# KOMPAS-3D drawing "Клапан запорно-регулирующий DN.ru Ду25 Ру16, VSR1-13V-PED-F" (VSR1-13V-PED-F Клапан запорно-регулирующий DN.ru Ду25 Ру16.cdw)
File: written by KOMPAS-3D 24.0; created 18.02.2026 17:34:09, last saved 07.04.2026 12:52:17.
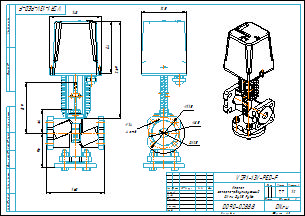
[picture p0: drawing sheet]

Document properties: Автор: R2D2; Форматы листов документа: A3; Полное имя файла: VSR1-13V-PED-F Клапан запорно-регулирующий DN.ru Ду25 Ру16.m3d; Масса: 7.7; Наименование: Клапан запорно-регулирующий DN.ru Ду25 Ру16; Количество листов документа: 1; Примечание: D090-02888

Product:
- Part/product: Клапан запорно-регулирующий DN.ru Ду25 Ру16  | designation VSR1-13V-PED-F
    Масса: 7.7
    Раздел спецификации: Прочие изделия
    Примечание: D090-02888

Views: Вид 1, Спереди
Referenced files in E:\Работа\Зайцев\Солянка\VSR1-13V-PED-F Клапан запорно-регулирующий DN.ru\DN15\DN15 Kv0.16\: VSR1-13V-PED-F Клапан запорно-регулирующий DN.ru Ду15 Ру16.m3d
Referenced files in E:\Работа\Зайцев\Солянка\VSR1-13V-PED-F Клапан запорно-регулирующий DN.ru\DN25\: VSR1-13V-PED-F Клапан запорно-регулирующий DN.ru Ду25 Ру16.m3d
Referenced files in E:\Работа\Зайцев\Для компаса\: чертеж DN.ru А3.cdt
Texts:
  Линейный размер
  VSR1-13V-PED-F
  чертеж DN.ru А3.cdt
  Клапан
  запорно-регулирующий
  DN.ru Ду25 Ру16
  Клапан запорно-регулирующий DN.ru Ду25 Ру16
  VSR1-13V-PED-F Клапан запорно-регулирующий DN.ru Ду25 Ру16
Dimensions and other numbers on the sheet: 0; 3; 2; 4; 160; 143; 64; 139; 96; 144; 269; 6; 1:2; 1; 7,7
